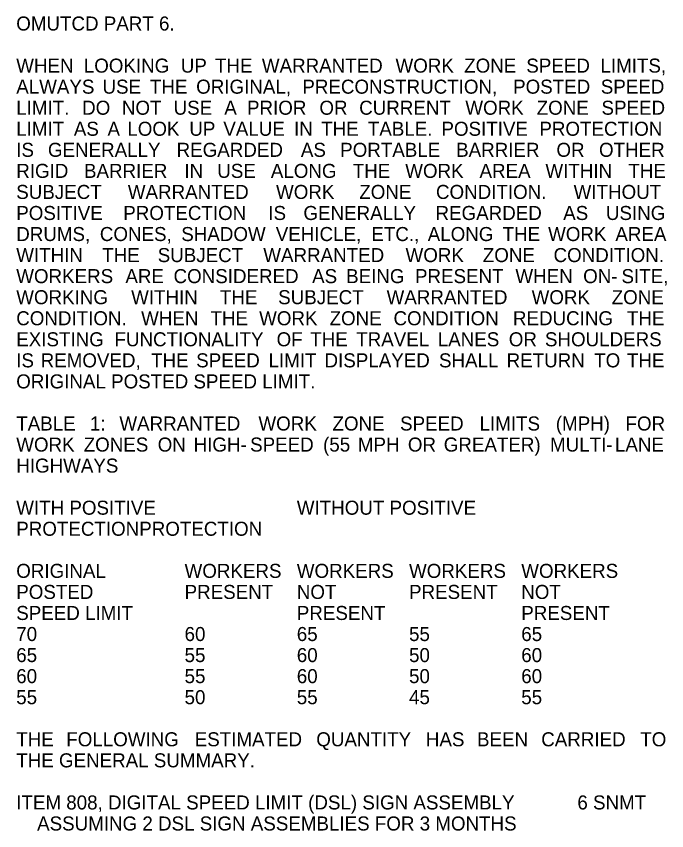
# Model space of a CAD drawing. Extents: x 0 to 43.6, y -18 to 22.
# Drawn here: x 37.09 to 43.58, y 0.91 to 9.03 of the extents above; entities that cross this region are included whole.
import ezdxf

# ---------------------------------------------------------------- set-up
doc = ezdxf.new("R2010")
doc.units = 0
doc.layers.add('SH_Text', color=7, linetype='Continuous')

msp = doc.modelspace()

# ---------------------------------------------------------------- texts
at = {"layer": 'SH_Text'}
for s, p in [('OMUTCD PART 6.', (37.0907, 8.89)), ('LOOKING ', (37.765, 8.47)), ('WORK ', (40.8759, 8.47)), ('ZONE ', (41.5611, 8.47)), ('SPEED ', (42.1811, 8.47)), ('LIMITS, ', (42.9211, 8.47)), ('WHEN ', (37.0907, 8.47)), ('UP ', (38.733, 8.47)), ('THE ', (39.0741, 8.47)), ('WARRANTED ', (39.542, 8.47)), ('ALWAYS ', (37.0907, 8.26)), ('USE ', (37.9514, 8.26)), ('THE ', (38.4244, 8.26)), ('ORIGINAL, ', (38.8863, 8.26)), ('PRECONSTRUCTION, ', (39.946, 8.26)), ('POSTED ', (42.0492, 8.26)), ('SPEED ', (42.9243, 8.26)), ('LIMIT. ', (37.0907, 8.05)), ('DO ', (37.7482, 8.05)), ('NOT ', (38.145, 8.05)), ('USE ', (38.6613, 8.05)), ('A ', (39.1669, 8.05)), ('PRIOR ', (39.3935, 8.05)), ('OR ', (40.1163, 8.05)), ('CURRENT ', (40.5131, 8.05)), ('WORK ', (41.5728, 8.05)), ('ZONE ', (42.2847, 8.05)), ('SPEED ', (42.9315, 8.05)), ('LIMIT ', (37.0907, 7.84)), ('AS ', (37.6655, 7.84)), ('A ', (38.0014, 7.84)), ('LOOK ', (38.1995, 7.84)), ('UP ', (38.818, 7.84)), ('VALUE ', (39.1574, 7.84)), ('IN ', (39.8631, 7.84)), ('THE ', (40.1336, 7.84)), ('TABLE. ', (40.5998, 7.84)), ('POSITIVE ', (41.3342, 7.84)), ('PROTECTION ', (42.3114, 7.84)), ('IS ', (37.0907, 7.63)), ('GENERALLY ', (37.4069, 7.63)), ('REGARDED ', (38.6911, 7.63)), ('AS ', (39.9312, 7.63)), ('PORTABLE ', (40.3236, 7.63)), ('BARRIER ', (41.4807, 7.63)), ('OR ', (42.4817, 7.63)), ('OTHER ', (42.9066, 7.63)), ('RIGID ', (37.0907, 7.42)), ('BARRIER ', (37.7666, 7.42)), ('IN ', (38.7688, 7.42)), ('USE ', (39.0969, 7.42)), ('ALONG ', (39.6317, 7.42)), ('THE ', (40.4491, 7.42)), ('WORK ', (40.9729, 7.42)), ('AREA ', (41.714, 7.42)), ('WITHIN ', (42.3721, 7.42)), ('THE ', (43.1999, 7.42)), ('SUBJECT ', (37.0907, 7.21)), ('WARRANTED ', (38.2042, 7.21)), ('WORK ', (39.6835, 7.21)), ('ZONE ', (40.5141, 7.21)), ('CONDITION. ', (41.2796, 7.21)), ('WITHOUT ', (42.6535, 7.21)), ('POSITIVE ', (37.0907, 7)), ('PROTECTION ', (38.1585, 7)), ('IS ', (39.6065, 7)), ('GENERALLY ', (39.9567, 7)), ('REGARDED ', (41.2749, 7)), ('AS ', (42.5491, 7)), ('USING ', (42.9756, 7)), ('DRUMS, ', (37.0907, 6.79)), ('CONES, ', (37.925, 6.79)), ('SHADOW ', (38.7376, 6.79)), ('VEHICLE, ', (39.6806, 6.79)), ('ETC., ', (40.6347, 6.79)), ('ALONG ', (41.1972, 6.79)), ('THE ', (41.9447, 6.79)), ('WORK ', (42.3986, 6.79)), ('AREA ', (43.0698, 6.79)), ('WITHIN ', (37.0907, 6.58)), ('THE ', (37.9485, 6.58)), ('SUBJECT ', (38.5024, 6.58)), ('WARRANTED ', (39.5563, 6.58)), ('WORK ', (40.976, 6.58)), ('ZONE ', (41.7471, 6.58)), ('CONDITION. ', (42.453, 6.58)), ('WORKERS ', (37.0907, 6.37)), ('ARE ', (38.18, 6.37)), ('CONSIDERED ', (38.6606, 6.37)), ('AS ', (40.0434, 6.37)), ('BEING ', (40.3828, 6.37)), ('PRESENT ', (41.0699, 6.37)), ('WHEN ', (42.0724, 6.37)), ('ON-', (42.7485, 6.37)), ('SITE, ', (43.1311, 6.37)), ('WORKING ', (37.0907, 6.16)), ('WITHIN ', (38.2374, 6.16)), ('THE ', (39.1231, 6.16)), ('SUBJECT ', (39.7048, 6.16)), ('WARRANTED ', (40.7867, 6.16)), ('WORK ', (42.2343, 6.16)), ('ZONE ', (43.0332, 6.16)), ('CONDITION. ', (37.0907, 5.95)), ('WHEN ', (38.337, 5.95)), ('THE ', (39.0291, 5.95)), ('WORK ', (39.5148, 5.95)), ('ZONE ', (40.2177, 5.95)), ('CONDITION ', (40.8556, 5.95)), ('REDUCING ', (42.0476, 5.95)), ('THE ', (43.1854, 5.95)), ('EXISTING ', (37.0907, 5.74)), ('FUNCTIONALITY ', (38.0712, 5.74)), ('OF ', (39.6892, 5.74)), ('THE ', (40.0247, 5.74)), ('TRAVEL ', (40.4834, 5.74)), ('LANES ', (41.2975, 5.74)), ('OR ', (42.0063, 5.74)), ('SHOULDERS ', (42.3671, 5.74)), ('IS ', (37.0907, 5.53)), ('REMOVED, ', (37.3343, 5.53)), ('THE ', (38.4366, 5.53)), ('SPEED ', (38.8866, 5.53)), ('LIMIT ', (39.6087, 5.53)), ('DISPLAYED ', (40.1672, 5.53)), ('SHALL ', (41.3096, 5.53)), ('RETURN ', (41.9846, 5.53)), ('TO ', (42.8585, 5.53)), ('THE ', (43.1854, 5.53)), ('ORIGINAL POSTED SPEED LIMIT.', (37.0907, 5.32)), ('TABLE ', (37.0907, 4.9)), ('1: ', (37.8265, 4.9)), ('WARRANTED ', (38.1201, 4.9)), ('WORK ', (39.5079, 4.9)), ('ZONE ', (40.247, 4.9)), ('SPEED ', (40.9209, 4.9)), ('LIMITS ', (41.7148, 4.9)), ('(MPH) ', (42.4756, 4.9)), ('FOR ', (43.1711, 4.9)), ('WORK ', (37.0907, 4.69)), ('ZONES ', (37.7639, 4.69)), ('ON ', (38.5024, 4.69)), ('HIGH-', (38.8604, 4.69)), ('SPEED ', (39.4248, 4.69)), ('(55 ', (40.1527, 4.69)), ('MPH ', (40.4998, 4.69)), ('OR ', (40.9991, 4.69)), ('GREATER) ', (41.3571, 4.69)), ('MULTI-', (42.418, 4.69)), ('LANE ', (43.0657, 4.69)), ('HIGHWAYS', (37.0907, 4.48)), ('WITH POSITIVE ', (37.0907, 4.06)), ('WITHOUT POSITIVE ', (39.8907, 4.06)), ('PROTECTIONPROTECTION ', (37.0907, 3.85)), ('ORIGINAL ', (37.0907, 3.43)), ('WORKERS', (38.7707, 3.43)), ('WORKERS', (39.8907, 3.43)), ('WORKERS', (41.0107, 3.43)), ('WORKERS', (42.1307, 3.43)), ('POSTED', (37.0907, 3.22)), ('PRESENT', (38.7707, 3.22)), ('NOT', (39.8907, 3.22)), ('PRESENT', (41.0107, 3.22)), ('NOT', (42.1307, 3.22)), ('SPEED LIMIT', (37.0907, 3.01)), ('PRESENT', (39.8907, 3.01)), ('PRESENT', (42.1307, 3.01)), ('70', (37.0907, 2.8)), ('60', (38.7707, 2.8)), ('65', (39.8907, 2.8)), ('55', (41.0107, 2.8)), ('65', (42.1307, 2.8)), ('65', (37.0907, 2.59)), ('55', (38.7707, 2.59)), ('60', (39.8907, 2.59)), ('50', (41.0107, 2.59)), ('60', (42.1307, 2.59)), ('60', (37.0907, 2.38)), ('55', (38.7707, 2.38)), ('60', (39.8907, 2.38)), ('50', (41.0107, 2.38)), ('60', (42.1307, 2.38)), ('55', (37.0907, 2.17)), ('50', (38.7707, 2.17)), ('55', (39.8907, 2.17)), ('45', (41.0107, 2.17)), ('55', (42.1307, 2.17)), ('THE ', (37.0907, 1.75)), ('FOLLOWING ', (37.5901, 1.75)), ('ESTIMATED ', (38.8719, 1.75)), ('QUANTITY ', (40.085, 1.75)), ('HAS ', (41.1787, 1.75)), ('BEEN ', (41.689, 1.75)), ('CARRIED ', (42.3299, 1.75)), ('TO ', (43.3184, 1.75)), ('THE GENERAL SUMMARY.', (37.0907, 1.54)), ('ITEM 808, DIGITAL SPEED LIMIT (DSL) SIGN ASSEMBLY', (37.0907, 1.12)), ('6 SNMT', (42.6907, 1.12)), ('    ASSUMING 2 DSL SIGN ASSEMBLIES FOR 3 MONTHS', (37.0907, 0.91))]:
    msp.add_text(s, height=0.14, dxfattribs=at).set_placement(p)

doc.saveas('drawing.dxf')
